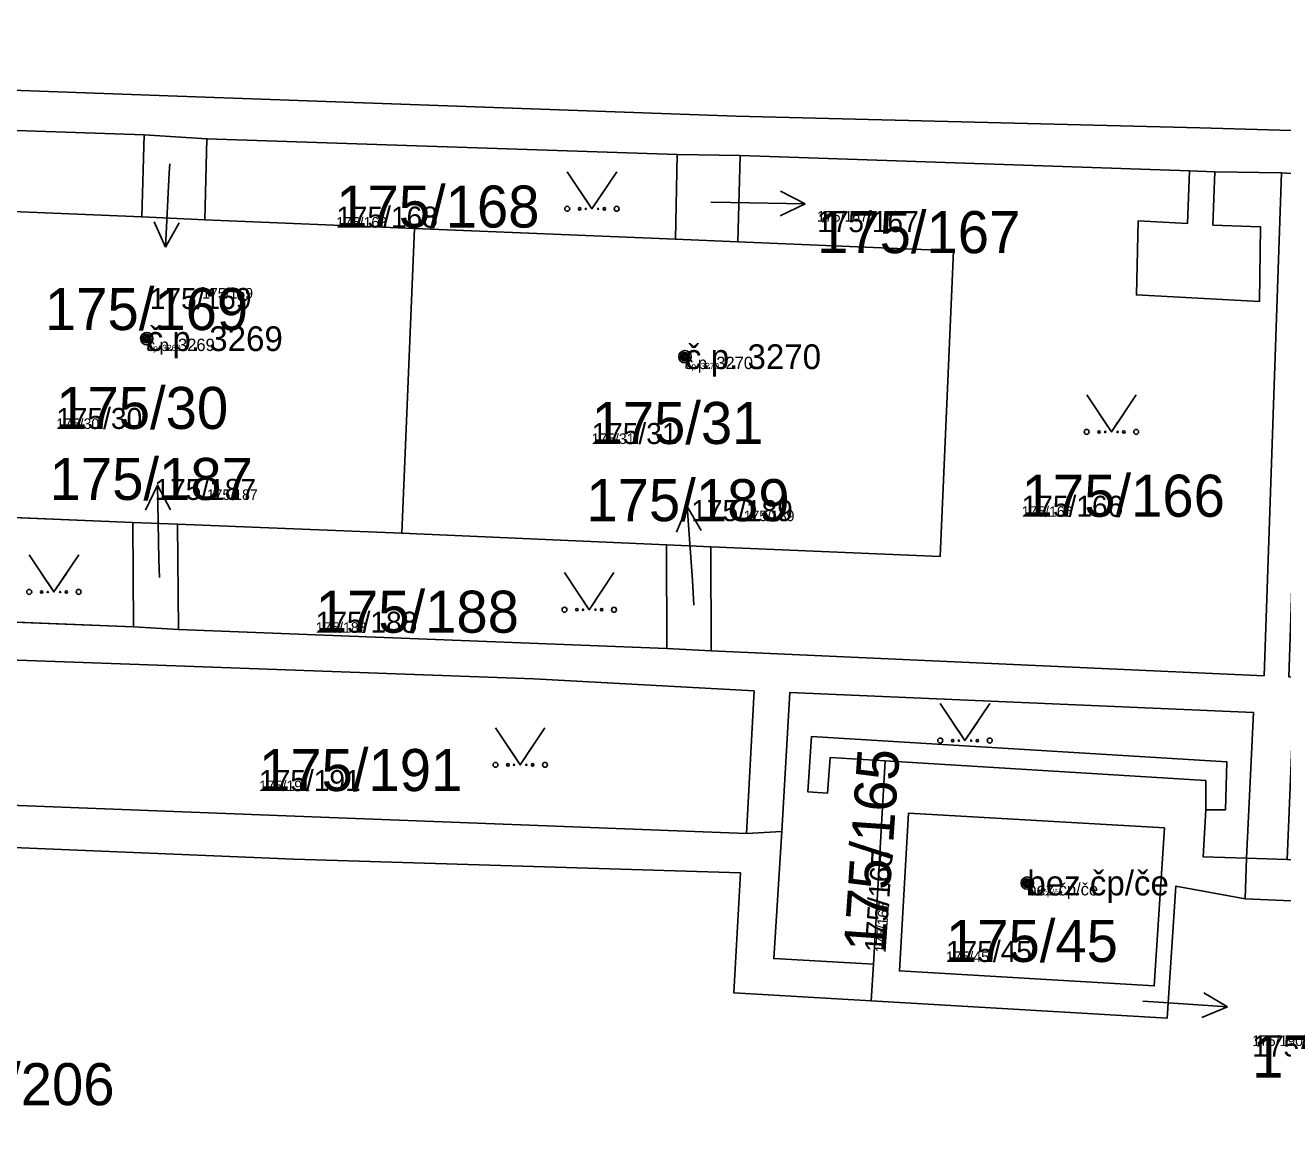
# Model space of a CAD drawing. Extents: x -759873 to -758487, y -975024 to -973516.
# Drawn here: x -759605.8 to -759554.9, y -974654.9 to -974610.2 of the extents above; entities that cross this region are included whole.
import ezdxf

# ---------------------------------------------------------------- set-up
doc = ezdxf.new("R2010")
doc.units = 0
for name, color, linetype in [('KAT_02_hranice parcel', 7, 'Continuous'), ('KAT_03_1000_st čísla parcelní', 7, 'Continuous'), ('KAT_03_1000_čísla parcelní', 7, 'Continuous'), ('KAT_03_1000_čísla popisná', 7, 'Continuous'), ('KAT_03_250_st čísla parcelní', 7, 'Continuous'), ('KAT_03_250_čísla parcelní', 7, 'Continuous'), ('KAT_03_250_čísla popisná', 7, 'Continuous'), ('KAT_03_500_st čísla parcelní', 7, 'Continuous'), ('KAT_03_500_čísla parcelní', 7, 'Continuous'), ('KAT_03_500_čísla popisná', 7, 'Continuous'), ('KAT_04_vnitřní kresba', 7, 'Continuous'), ('KAT_05_1000_značky kultur', 7, 'Continuous'), ('KAT_05_250_značky kultur', 7, 'Continuous'), ('KAT_05_500_značky kultur', 7, 'Continuous'), ('KAT_07_1000_značky budov', 7, 'Continuous'), ('KAT_07_250_značky budov', 7, 'Continuous'), ('KAT_07_500_značky budov', 7, 'Continuous'), ('KAT_12_pomocná šipka', 7, 'Continuous'), ('KAT_14_plocha_budovy', 7, 'Continuous'), ('KAT_14_plocha_pozemek', 7, 'Continuous')]:
    doc.layers.add(name, color=color, linetype=linetype)

msp = doc.modelspace()

# ---------------------------------------------------------------- linework, layer by layer
at = {"layer": 'KAT_02_hranice parcel'}
for p, q in [((-759620.45, -974614.02), (-759600.97, -974614.68)), ((-759600.97, -974614.68), (-759601.06, -974618)), ((-759600.97, -974614.68), (-759598.43, -974614.84)), ((-759598.43, -974614.84), (-759598.51, -974618.11)), ((-759598.43, -974614.84), (-759579.41, -974615.48)), ((-759579.41, -974615.48), (-759579.49, -974618.9)), ((-759579.41, -974615.48), (-759576.87, -974615.52)), ((-759576.87, -974615.52), (-759576.96, -974619.01)), ((-759554.99, -974616.21), (-759554, -974616.28)), ((-759598.51, -974618.11), (-759601.06, -974618)), ((-759590.04, -974618.46), (-759598.51, -974618.11)), ((-759590.55, -974630.79), (-759590.04, -974618.46)), ((-759579.49, -974618.9), (-759590.04, -974618.46)), ((-759576.96, -974619.01), (-759579.49, -974618.9)), ((-759612.32, -974629.9), (-759601.42, -974630.35)), ((-759601.42, -974630.35), (-759599.62, -974630.42)), ((-759601.39, -974634.57), (-759601.42, -974630.35)), ((-759599.62, -974630.42), (-759590.55, -974630.79)), ((-759599.58, -974634.68), (-759599.62, -974630.42)), ((-759590.55, -974630.79), (-759579.85, -974631.25)), ((-759579.85, -974631.25), (-759578.05, -974631.33)), ((-759579.84, -974635.44), (-759579.85, -974631.25)), ((-759578.05, -974631.33), (-759578.04, -974635.54)), ((-759601.39, -974634.57), (-759621.66, -974633.76)), ((-759599.58, -974634.68), (-759601.39, -974634.57)), ((-759579.84, -974635.44), (-759599.58, -974634.68)), ((-759578.04, -974635.54), (-759579.84, -974635.44)), ((-759576.61, -974642.92), (-759575.19, -974642.84)), ((-759556.45, -974645.57), (-759556.4, -974643.92)), ((-759556.4, -974643.92), (-759554.75, -974643.98)), ((-759571.48, -974648.21), (-759571.57, -974649.69))]:
    msp.add_line(p, q, dxfattribs=at)
for points in [[(-759748.01, -974589.58), (-759742.78, -974592.68), (-759732.01, -974598.91), (-759728.99, -974600.68), (-759725.4, -974602.45), (-759718.02, -974604.75), (-759709.84, -974606.71), (-759702.63, -974608.03), (-759689.82, -974608.95), (-759677.23, -974609.87), (-759664.06, -974610.49), (-759641.64, -974611.43), (-759620.48, -974612.36), (-759598.5, -974613.15), (-759577.03, -974613.93), (-759558.28, -974614.4), (-759534.22, -974615.1), (-759512.72, -974615.61), (-759490.5, -974616.02), (-759471.82, -974616.25), (-759458.92, -974616), (-759446.09, -974615.46)], [(-759576.87, -974615.52), (-759558.71, -974616.14), (-759558.79, -974618.27), (-759560.78, -974618.16), (-759560.85, -974621.15), (-759555.88, -974621.42), (-759555.83, -974618.4), (-759557.76, -974618.33), (-759557.68, -974616.18), (-759554.99, -974616.21)], [(-759554.99, -974616.21), (-759555.69, -974636.55), (-759578.04, -974635.54)], [(-759601.06, -974618), (-759611.82, -974617.55), (-759611.87, -974618.75)], [(-759578.05, -974631.33), (-759568.79, -974631.73), (-759568.25, -974619.37), (-759576.96, -974619.01)], [(-759608.85, -974641.69), (-759608.73, -974635.83), (-759601.54, -974636.08), (-759585.21, -974636.67), (-759576.31, -974637.16), (-759576.61, -974642.92)], [(-759575.19, -974642.84), (-759574.86, -974637.22), (-759556.11, -974638.04), (-759556.4, -974643.92)], [(-759571.48, -974648.21), (-759571.01, -974639.99), (-759573.23, -974639.85), (-759573.34, -974641.3), (-759574.14, -974641.24), (-759573.98, -974639), (-759557.19, -974640.03), (-759557.25, -974641.97), (-759558.04, -974641.97), (-759558.15, -974643.87), (-759556.4, -974643.92)], [(-759715.4, -974658.58), (-759700.76, -974652.49), (-759684.23, -974647.96), (-759662.52, -974646.3), (-759662.17, -974641.26), (-759630.55, -974642.48), (-759594.91, -974643.96), (-759576.85, -974644.52), (-759577.12, -974649.37), (-759571.57, -974649.69)], [(-759608.85, -974641.69), (-759595.23, -974642.21), (-759576.61, -974642.92)], [(-759559.72, -974642.7), (-759570.07, -974642.11), (-759570.43, -974648.48), (-759560.13, -974649.09), (-759559.72, -974642.7)], [(-759575.19, -974642.84), (-759575.51, -974647.98), (-759571.48, -974648.21)], [(-759571.57, -974649.69), (-759559.6, -974650.39), (-759559.25, -974645.05), (-759556.45, -974645.57)], [(-759301.4, -974651.09), (-759309.93, -974650.8), (-759309.98, -974645.76), (-759323.06, -974645.78), (-759353.1, -974645.55), (-759386.38, -974645.33), (-759400.57, -974645.67), (-759414.93, -974646.26), (-759414.73, -974651.33), (-759436.14, -974652.5), (-759441.93, -974652.85), (-759450.38, -974653.47), (-759468.91, -974653.71), (-759482.38, -974653.4), (-759482.33, -974648.6), (-759512.45, -974647.4), (-759531.67, -974646.64), (-759556.45, -974645.57)]]:
    msp.add_lwpolyline(points, dxfattribs=at)
at = {"layer": 'KAT_03_1000_čísla popisná'}
for centre in [(-759600.86, -974622.92), (-759579.1, -974623.65), (-759565.26, -974644.93)]:
    msp.add_circle(centre, 0.25, dxfattribs=at)
at = {"layer": 'KAT_03_250_čísla popisná'}
for centre in [(-759600.86, -974622.92), (-759579.1, -974623.65), (-759565.26, -974644.93)]:
    msp.add_circle(centre, 0.0625, dxfattribs=at)
at = {"layer": 'KAT_03_500_čísla popisná'}
for centre in [(-759600.86, -974622.92), (-759579.1, -974623.65), (-759565.26, -974644.93)]:
    msp.add_circle(centre, 0.125, dxfattribs=at)
at = {"layer": 'KAT_04_vnitřní kresba'}
for p, q in [((-759558.71, -974616.14), (-759557.68, -974616.18)), ((-759571.01, -974639.99), (-759558.04, -974640.78)), ((-759558.04, -974641.97), (-759558.04, -974640.78))]:
    msp.add_line(p, q, dxfattribs=at)
at = {"layer": 'KAT_05_1000_značky kultur'}
for points in [[(-759583.86, -974616.169), (-759582.86, -974617.67), (-759581.86, -974616.169)], [(-759562.86, -974625.189), (-759561.86, -974626.69), (-759560.86, -974625.189)], [(-759605.61, -974631.659), (-759604.61, -974633.16), (-759603.61, -974631.659)], [(-759583.97, -974632.379), (-759582.97, -974633.88), (-759581.97, -974632.379)], [(-759568.78, -974637.669), (-759567.78, -974639.17), (-759566.78, -974637.669)], [(-759586.76, -974638.649), (-759585.76, -974640.15), (-759584.76, -974638.649)]]:
    msp.add_lwpolyline(points, dxfattribs=at)
for centre in [(-759583.86, -974617.669), (-759581.86, -974617.669), (-759562.86, -974626.689), (-759560.86, -974626.689), (-759605.61, -974633.159), (-759603.61, -974633.159), (-759583.97, -974633.879), (-759581.97, -974633.879), (-759568.78, -974639.169), (-759566.78, -974639.169), (-759586.76, -974640.149), (-759584.76, -974640.149)]:
    msp.add_circle(centre, 0.1, dxfattribs=at)
at = {"layer": 'KAT_05_250_značky kultur'}
for points in [[(-759583.11, -974617.295), (-759582.86, -974617.67), (-759582.61, -974617.295)], [(-759562.11, -974626.315), (-759561.86, -974626.69), (-759561.61, -974626.315)], [(-759604.86, -974632.785), (-759604.61, -974633.16), (-759604.36, -974632.785)], [(-759583.22, -974633.505), (-759582.97, -974633.88), (-759582.72, -974633.505)], [(-759568.03, -974638.795), (-759567.78, -974639.17), (-759567.53, -974638.795)], [(-759586.01, -974639.775), (-759585.76, -974640.15), (-759585.51, -974639.775)]]:
    msp.add_lwpolyline(points, dxfattribs=at)
for centre in [(-759583.11, -974617.67), (-759582.61, -974617.67), (-759562.11, -974626.69), (-759561.61, -974626.69), (-759604.86, -974633.16), (-759604.36, -974633.16), (-759583.22, -974633.88), (-759582.72, -974633.88), (-759568.03, -974639.17), (-759567.53, -974639.17), (-759586.01, -974640.15), (-759585.51, -974640.15)]:
    msp.add_circle(centre, 0.025, dxfattribs=at)
at = {"layer": 'KAT_05_500_značky kultur'}
for points in [[(-759583.36, -974616.92), (-759582.86, -974617.67), (-759582.36, -974616.92)], [(-759562.36, -974625.939), (-759561.86, -974626.69), (-759561.36, -974625.939)], [(-759605.11, -974632.41), (-759604.61, -974633.16), (-759604.11, -974632.41)], [(-759583.47, -974633.13), (-759582.97, -974633.88), (-759582.47, -974633.13)], [(-759568.28, -974638.42), (-759567.78, -974639.17), (-759567.28, -974638.42)], [(-759586.26, -974639.4), (-759585.76, -974640.15), (-759585.26, -974639.4)]]:
    msp.add_lwpolyline(points, dxfattribs=at)
for centre in [(-759583.36, -974617.67), (-759582.36, -974617.67), (-759562.36, -974626.69), (-759561.36, -974626.69), (-759605.11, -974633.16), (-759604.11, -974633.16), (-759583.47, -974633.88), (-759582.47, -974633.88), (-759568.28, -974639.17), (-759567.28, -974639.17), (-759586.26, -974640.15), (-759585.26, -974640.15)]:
    msp.add_circle(centre, 0.05, dxfattribs=at)
at = {"layer": 'KAT_07_1000_značky budov'}
for centre in [(-759600.867, -974622.919), (-759579.107, -974623.649), (-759565.267, -974644.929)]:
    msp.add_circle(centre, 0.175, dxfattribs=at)
at = {"layer": 'KAT_07_250_značky budov'}
for centre in [(-759600.862, -974622.92), (-759579.102, -974623.65), (-759565.262, -974644.93)]:
    msp.add_circle(centre, 0.0437, dxfattribs=at)
at = {"layer": 'KAT_07_500_značky budov'}
for centre in [(-759600.863, -974622.92), (-759579.103, -974623.65), (-759565.263, -974644.93)]:
    msp.add_circle(centre, 0.0875, dxfattribs=at)
at = {"layer": 'KAT_12_pomocná šipka'}
for p, q in [((-759599.95, -974616.22), (-759600.107, -974619.217)), ((-759599.93, -974615.85), (-759599.95, -974616.22)), ((-759574.239, -974617.472), (-759575.232, -974616.954)), ((-759578.05, -974617.4), (-759577.24, -974617.42)), ((-759577.24, -974617.42), (-759574.239, -974617.472)), ((-759574.239, -974617.472), (-759575.25, -974617.956)), ((-759600.107, -974619.217), (-759600.555, -974618.191)), ((-759600.107, -974619.217), (-759599.555, -974618.243)), ((-759600.422, -974628.849), (-759600.906, -974629.86)), ((-759600.37, -974631.85), (-759600.422, -974628.849)), ((-759600.422, -974628.849), (-759599.904, -974629.842)), ((-759579.009, -974629.706), (-759579.439, -974630.74)), ((-759578.8, -974632.7), (-759579.009, -974629.706)), ((-759579.009, -974629.706), (-759578.44, -974630.67)), ((-759600.35, -974632.58), (-759600.37, -974631.85)), ((-759578.74, -974633.69), (-759578.8, -974632.7)), ((-759557.166, -974649.939), (-759558.13, -974649.37)), ((-759560.59, -974649.7), (-759560.16, -974649.73)), ((-759560.16, -974649.73), (-759557.166, -974649.939)), ((-759557.166, -974649.939), (-759558.2, -974650.369))]:
    msp.add_line(p, q, dxfattribs=at)
at = {"layer": 'KAT_14_plocha_budovy'}
for points in [[(-759612.32, -974629.9), (-759601.42, -974630.35), (-759599.62, -974630.42), (-759590.55, -974630.79), (-759590.04, -974618.46), (-759598.51, -974618.11), (-759601.06, -974618), (-759611.82, -974617.55), (-759611.87, -974618.75)], [(-759590.55, -974630.79), (-759579.85, -974631.25), (-759578.05, -974631.33), (-759568.79, -974631.73), (-759568.25, -974619.37), (-759576.96, -974619.01), (-759579.49, -974618.9), (-759590.04, -974618.46)], [(-759570.43, -974648.48), (-759560.13, -974649.09), (-759559.72, -974642.7), (-759570.07, -974642.11)]]:
    msp.add_lwpolyline(points, close=True, dxfattribs=at)
at = {"layer": 'KAT_14_plocha_pozemek'}
for points in [[(-759446.09, -974615.46), (-759458.92, -974616), (-759471.82, -974616.25), (-759490.5, -974616.02), (-759512.72, -974615.61), (-759534.22, -974615.1), (-759558.28, -974614.4), (-759577.03, -974613.93), (-759598.5, -974613.15), (-759620.48, -974612.36)], [(-759620.48, -974612.36), (-759598.5, -974613.15), (-759577.03, -974613.93), (-759558.28, -974614.4), (-759534.22, -974615.1), (-759512.72, -974615.61), (-759490.5, -974616.02), (-759471.82, -974616.25), (-759458.92, -974616), (-759446.09, -974615.46)], [(-759620.45, -974614.02), (-759600.97, -974614.68), (-759598.43, -974614.84), (-759579.41, -974615.48), (-759576.87, -974615.52), (-759558.71, -974616.14), (-759558.79, -974618.27), (-759560.78, -974618.16), (-759560.85, -974621.15), (-759555.88, -974621.42), (-759555.83, -974618.4), (-759557.76, -974618.33), (-759557.68, -974616.18), (-759554.99, -974616.21), (-759554, -974616.28)], [(-759453.76, -974638.72), (-759465.53, -974640.52), (-759470.44, -974640.27), (-759471.91, -974640.21), (-759491.95, -974639.29), (-759493.45, -974639.25), (-759514.11, -974638.35), (-759515.58, -974638.24), (-759535.52, -974637.39), (-759537, -974637.31), (-759554.69, -974636.59), (-759554, -974616.28), (-759554.99, -974616.21), (-759555.69, -974636.55), (-759578.04, -974635.54), (-759579.84, -974635.44), (-759599.58, -974634.68), (-759601.39, -974634.57), (-759621.66, -974633.76)], [(-759608.73, -974635.83), (-759601.54, -974636.08), (-759585.21, -974636.67), (-759576.31, -974637.16), (-759576.61, -974642.92), (-759575.19, -974642.84), (-759574.86, -974637.22), (-759556.11, -974638.04), (-759556.4, -974643.92), (-759554.75, -974643.98), (-759554.51, -974638.11), (-759537.36, -974638.86), (-759515.58, -974639.78), (-759506.13, -974640.2), (-759506.15, -974646.02), (-759504.71, -974646.1), (-759504.3, -974640.26), (-759492.11, -974640.81), (-759471.99, -974641.69), (-759465.33, -974642.08), (-759453.67, -974640.38)], [(-759630.55, -974642.48), (-759594.91, -974643.96), (-759576.85, -974644.52), (-759577.12, -974649.37), (-759571.57, -974649.69), (-759571.48, -974648.21), (-759575.51, -974647.98), (-759575.19, -974642.84), (-759576.61, -974642.92), (-759595.23, -974642.21), (-759608.85, -974641.69)], [(-759450.38, -974653.47), (-759468.91, -974653.71), (-759482.38, -974653.4), (-759482.33, -974648.6), (-759512.45, -974647.4), (-759531.67, -974646.64), (-759556.45, -974645.57), (-759559.25, -974645.05), (-759559.6, -974650.39), (-759571.57, -974649.69), (-759577.12, -974649.37), (-759576.85, -974644.52), (-759594.91, -974643.96), (-759630.55, -974642.48)], [(-759455.76, -974651.64), (-759457.23, -974651.73), (-759469.03, -974651.9), (-759480.7, -974651.84), (-759480.58, -974647.06), (-759504.71, -974646.1), (-759506.15, -974646.02), (-759531.77, -974645.02), (-759554.75, -974643.98), (-759556.4, -974643.92), (-759556.45, -974645.57), (-759531.67, -974646.64), (-759512.45, -974647.4), (-759482.33, -974648.6), (-759482.38, -974653.4), (-759468.91, -974653.71), (-759450.38, -974653.47)]]:
    msp.add_lwpolyline(points, dxfattribs=at)
for points in [[(-759620.45, -974614.02), (-759620.62, -974618.39), (-759611.87, -974618.75), (-759611.82, -974617.55), (-759601.06, -974618), (-759600.97, -974614.68)], [(-759600.97, -974614.68), (-759601.06, -974618), (-759598.51, -974618.11), (-759598.43, -974614.84)], [(-759598.43, -974614.84), (-759598.51, -974618.11), (-759590.04, -974618.46), (-759579.49, -974618.9), (-759579.41, -974615.48)], [(-759579.41, -974615.48), (-759579.49, -974618.9), (-759576.96, -974619.01), (-759576.87, -974615.52)], [(-759576.87, -974615.52), (-759576.96, -974619.01), (-759568.25, -974619.37), (-759568.79, -974631.73), (-759578.05, -974631.33), (-759578.04, -974635.54), (-759555.69, -974636.55), (-759554.99, -974616.21), (-759557.68, -974616.18), (-759557.76, -974618.33), (-759555.83, -974618.4), (-759555.88, -974621.42), (-759560.85, -974621.15), (-759560.78, -974618.16), (-759558.79, -974618.27), (-759558.71, -974616.14)], [(-759590.04, -974618.46), (-759598.51, -974618.11), (-759601.06, -974618), (-759611.82, -974617.55), (-759611.87, -974618.75), (-759612.32, -974629.9), (-759601.42, -974630.35), (-759599.62, -974630.42), (-759590.55, -974630.79)], [(-759579.49, -974618.9), (-759590.04, -974618.46), (-759590.55, -974630.79), (-759579.85, -974631.25), (-759578.05, -974631.33), (-759568.79, -974631.73), (-759568.25, -974619.37), (-759576.96, -974619.01)], [(-759601.39, -974634.57), (-759601.42, -974630.35), (-759612.32, -974629.9), (-759612.48, -974631.11), (-759621.74, -974630.73), (-759621.66, -974633.76)], [(-759599.58, -974634.68), (-759599.62, -974630.42), (-759601.42, -974630.35), (-759601.39, -974634.57)], [(-759579.84, -974635.44), (-759579.85, -974631.25), (-759590.55, -974630.79), (-759599.62, -974630.42), (-759599.58, -974634.68)], [(-759578.05, -974631.33), (-759579.85, -974631.25), (-759579.84, -974635.44), (-759578.04, -974635.54)], [(-759576.61, -974642.92), (-759576.31, -974637.16), (-759585.21, -974636.67), (-759601.54, -974636.08), (-759608.73, -974635.83), (-759608.85, -974641.69), (-759595.23, -974642.21)], [(-759571.01, -974639.99), (-759573.23, -974639.85), (-759573.34, -974641.3), (-759574.14, -974641.24), (-759573.98, -974639), (-759557.19, -974640.03), (-759557.25, -974641.97), (-759558.04, -974641.97), (-759558.15, -974643.87), (-759556.4, -974643.92), (-759556.11, -974638.04), (-759574.86, -974637.22), (-759575.19, -974642.84), (-759575.51, -974647.98), (-759571.48, -974648.21)], [(-759559.6, -974650.39), (-759559.25, -974645.05), (-759556.45, -974645.57), (-759556.4, -974643.92), (-759558.15, -974643.87), (-759558.04, -974641.97), (-759557.25, -974641.97), (-759557.19, -974640.03), (-759573.98, -974639), (-759574.14, -974641.24), (-759573.34, -974641.3), (-759573.23, -974639.85), (-759571.01, -974639.99), (-759571.48, -974648.21), (-759571.57, -974649.69)], [(-759559.72, -974642.7), (-759570.07, -974642.11), (-759570.43, -974648.48), (-759560.13, -974649.09)], [(-759559.72, -974642.7), (-759560.13, -974649.09), (-759570.43, -974648.48), (-759570.07, -974642.11)]]:
    msp.add_lwpolyline(points, close=True, dxfattribs=at)

# ---------------------------------------------------------------- texts
at = {"layer": 'KAT_03_1000_st čísla parcelní'}
for s, p in [('175/30', (-759604.52, -974626.57)), ('175/31', (-759582.88, -974627.179)), ('175/45', (-759568.55, -974648.12))]:
    msp.add_text(s, height=1.7, dxfattribs=at).set_placement(p)
at = {"layer": 'KAT_03_1000_čísla parcelní'}
for s, p in [('175/168', (-759593.2, -974618.429)), ('175/167', (-759573.76, -974619.463)), ('175/169', (-759604.976, -974622.573)), ('175/187', (-759604.786, -974629.44)), ('175/189', (-759583.086, -974630.299)), ('175/166', (-759565.49, -974630.12)), ('175/188', (-759594.03, -974634.809)), ('175/191', (-759596.32, -974641.21)), ('175/190', (-759556.17, -974652.793)), ('175/206', (-759610.38, -974653.91))]:
    msp.add_text(s, height=1.7, dxfattribs=at).set_placement(p)
msp.add_text('175/165', height=1.7, rotation=86, dxfattribs=at).set_placement((-759570.992, -974647.759))
at = {"layer": 'KAT_03_1000_čísla popisná'}
for s, p in [('č.p. 3269', (-759600.86, -974623.42)), ('č.p. 3270', (-759579.1, -974624.15)), ('bez čp/če', (-759565.26, -974645.43))]:
    msp.add_text(s, height=1, dxfattribs=at).set_placement(p)
at = {"layer": 'KAT_03_250_st čísla parcelní'}
for s, p in [('175/30', (-759604.52, -974626.57)), ('175/31', (-759582.88, -974627.179)), ('175/45', (-759568.55, -974648.12))]:
    msp.add_text(s, height=0.425, dxfattribs=at).set_placement(p)
at = {"layer": 'KAT_03_250_čísla parcelní'}
for s, p in [('175/167', (-759573.76, -974618.188)), ('175/168', (-759593.2, -974618.429)), ('175/169', (-759598.618, -974621.298)), ('175/187', (-759598.43, -974629.44)), ('175/189', (-759576.728, -974630.299)), ('175/166', (-759565.49, -974630.12)), ('175/188', (-759594.03, -974634.809)), ('175/191', (-759596.32, -974641.21)), ('175/190', (-759556.17, -974651.518))]:
    msp.add_text(s, height=0.425, dxfattribs=at).set_placement(p)
msp.add_text('175/165', height=0.425, rotation=86, dxfattribs=at).set_placement((-759570.992, -974647.759))
at = {"layer": 'KAT_03_250_čísla popisná'}
for s, p in [('č.p. 3269', (-759600.86, -974623.42)), ('č.p. 3270', (-759579.1, -974624.15)), ('bez čp/če', (-759565.26, -974645.43))]:
    msp.add_text(s, height=0.25, dxfattribs=at).set_placement(p)
at = {"layer": 'KAT_03_500_st čísla parcelní'}
for s, p in [('175/30', (-759604.52, -974626.57)), ('175/31', (-759582.88, -974627.179)), ('175/45', (-759568.55, -974648.12))]:
    msp.add_text(s, height=0.85, dxfattribs=at).set_placement(p)
at = {"layer": 'KAT_03_500_čísla parcelní'}
for s, p in [('175/168', (-759593.2, -974618.429)), ('175/167', (-759573.76, -974618.613)), ('175/169', (-759600.738, -974621.723)), ('175/187', (-759600.549, -974629.44)), ('175/189', (-759578.848, -974630.299)), ('175/166', (-759565.49, -974630.12)), ('175/188', (-759594.03, -974634.809)), ('175/191', (-759596.32, -974641.21)), ('175/190', (-759556.17, -974651.943))]:
    msp.add_text(s, height=0.85, dxfattribs=at).set_placement(p)
msp.add_text('175/165', height=0.85, rotation=86, dxfattribs=at).set_placement((-759570.992, -974647.759))
at = {"layer": 'KAT_03_500_čísla popisná'}
for s, p in [('č.p. 3269', (-759600.86, -974623.42)), ('č.p. 3270', (-759579.1, -974624.15)), ('bez čp/če', (-759565.26, -974645.43))]:
    msp.add_text(s, height=0.5, dxfattribs=at).set_placement(p)

doc.saveas('drawing.dxf')
